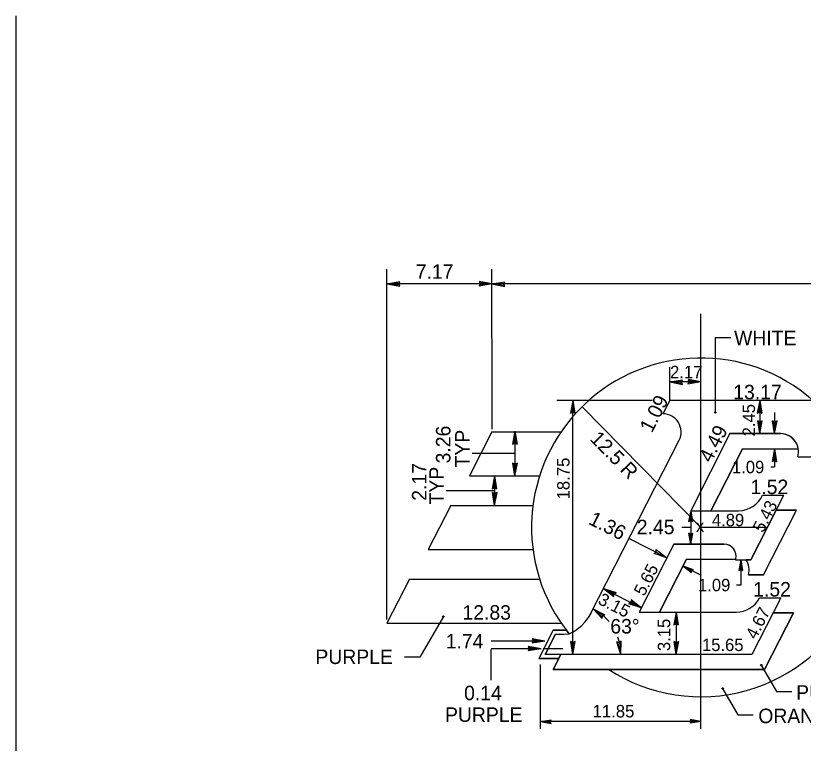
# Model space of a CAD drawing. Extents: x 10268197 to 10268826, y 2141503 to 2142677.
# Drawn here: x 10268664.32 to 10268696.97, y 2142401.45 to 2142431.59 of the extents above; entities that cross this region are included whole.
import ezdxf

# ---------------------------------------------------------------- set-up
doc = ezdxf.new("R2010")
doc.units = 0
doc.layers.add('Default', color=7, linetype='Continuous')
doc.layers.add('NonPlottingEle_dp', color=7, linetype='Continuous')

msp = doc.modelspace()

# ---------------------------------------------------------------- linework, layer by layer
at = {"layer": 'Default'}
for p, q in [((10268679.71, 2142406.582), (10268679.71, 2142421.09)), ((10268684.065, 2142415.347), (10268684.064, 2142421.09)), ((10268679.71, 2142420.48), (10268680.243, 2142420.574)), ((10268679.71, 2142420.48), (10268680.221, 2142420.524)), ((10268684.064, 2142420.48), (10268679.71, 2142420.48)), ((10268679.71, 2142420.48), (10268680.243, 2142420.386)), ((10268679.71, 2142420.48), (10268680.222, 2142420.435)), ((10268680.202, 2142420.48), (10268680.243, 2142420.574)), ((10268680.243, 2142420.386), (10268680.202, 2142420.48)), ((10268684.064, 2142420.48), (10268683.531, 2142420.574)), ((10268683.531, 2142420.574), (10268683.572, 2142420.48)), ((10268684.064, 2142420.48), (10268683.531, 2142420.386)), ((10268683.572, 2142420.48), (10268683.531, 2142420.386)), ((10268684.064, 2142420.48), (10268683.553, 2142420.524)), ((10268684.064, 2142420.48), (10268683.553, 2142420.435)), ((10268684.064, 2142420.48), (10268684.599, 2142420.565)), ((10268684.064, 2142420.48), (10268684.576, 2142420.516)), ((10268724.378, 2142420.48), (10268684.064, 2142420.48)), ((10268684.064, 2142420.48), (10268684.595, 2142420.377)), ((10268684.064, 2142420.48), (10268684.575, 2142420.426)), ((10268684.556, 2142420.471), (10268684.599, 2142420.565)), ((10268684.595, 2142420.377), (10268684.556, 2142420.471)), ((10268692.721, 2142410.391), (10268692.721, 2142419.238)), ((10268693.322, 2142418.257), (10268693.965, 2142418.258)), ((10268693.322, 2142415.153), (10268693.322, 2142418.257)), ((10268691.433, 2142415.653), (10268691.433, 2142417.027)), ((10268692.721, 2142416.417), (10268692.189, 2142416.52)), ((10268692.189, 2142416.52), (10268692.228, 2142416.425)), ((10268691.433, 2142416.417), (10268691.967, 2142416.501)), ((10268691.433, 2142416.417), (10268691.945, 2142416.453)), ((10268692.721, 2142416.417), (10268691.433, 2142416.417)), ((10268691.433, 2142416.417), (10268691.964, 2142416.314)), ((10268691.433, 2142416.417), (10268691.943, 2142416.363)), ((10268691.925, 2142416.408), (10268691.967, 2142416.501)), ((10268691.964, 2142416.314), (10268691.925, 2142416.408)), ((10268692.228, 2142416.425), (10268692.186, 2142416.332)), ((10268692.721, 2142416.417), (10268692.186, 2142416.332)), ((10268692.721, 2142416.417), (10268692.209, 2142416.381)), ((10268692.721, 2142416.417), (10268692.21, 2142416.47)), ((10268690.715, 2142415.653), (10268686.746, 2142415.654)), ((10268687.415, 2142415.653), (10268687.312, 2142415.122)), ((10268687.415, 2142415.653), (10268687.361, 2142415.142)), ((10268687.415, 2142405.129), (10268687.415, 2142415.653)), ((10268687.415, 2142415.653), (10268687.5, 2142415.119)), ((10268687.415, 2142415.653), (10268687.451, 2142415.141)), ((10268691.433, 2142415.653), (10268691.148, 2142415.096)), ((10268698.825, 2142415.653), (10268691.433, 2142415.653)), ((10268695.162, 2142415.653), (10268695.059, 2142415.122)), ((10268695.162, 2142415.653), (10268695.108, 2142415.142)), ((10268695.162, 2142415.653), (10268695.162, 2142414.275)), ((10268695.162, 2142415.653), (10268695.247, 2142415.119)), ((10268695.162, 2142415.653), (10268695.198, 2142415.141)), ((10268684.065, 2142414.457), (10268684.065, 2142415.347)), ((10268692.721, 2142410.391), (10268687.797, 2142415.39)), ((10268687.312, 2142415.122), (10268687.406, 2142415.161)), ((10268687.406, 2142415.161), (10268687.5, 2142415.119)), ((10268695.059, 2142415.122), (10268695.153, 2142415.161)), ((10268695.153, 2142415.161), (10268695.247, 2142415.119)), ((10268695.778, 2142415.155), (10268695.778, 2142414.275)), ((10268695.162, 2142414.275), (10268695.077, 2142414.81)), ((10268695.17, 2142414.768), (10268695.077, 2142414.81)), ((10268695.162, 2142414.275), (10268695.126, 2142414.787)), ((10268695.162, 2142414.275), (10268695.265, 2142414.807)), ((10268695.162, 2142414.275), (10268695.215, 2142414.786)), ((10268695.265, 2142414.807), (10268695.17, 2142414.768)), ((10268695.778, 2142414.275), (10268695.693, 2142414.81)), ((10268695.787, 2142414.767), (10268695.693, 2142414.81)), ((10268695.778, 2142414.275), (10268695.742, 2142414.787)), ((10268695.778, 2142414.275), (10268695.881, 2142414.807)), ((10268695.778, 2142414.275), (10268695.832, 2142414.786)), ((10268695.881, 2142414.807), (10268695.787, 2142414.767)), ((10268684.064, 2142414.351), (10268683.132, 2142412.521)), ((10268684.064, 2142414.351), (10268686.928, 2142414.351)), ((10268685.016, 2142414.374), (10268684.913, 2142413.843)), ((10268685.016, 2142414.374), (10268684.962, 2142413.864)), ((10268685.016, 2142414.374), (10268685.016, 2142412.521)), ((10268685.016, 2142414.374), (10268685.101, 2142413.84)), ((10268685.016, 2142414.374), (10268685.052, 2142413.862)), ((10268693.927, 2142414.275), (10268692.3, 2142411.08)), ((10268693.927, 2142414.275), (10268692.3, 2142411.08)), ((10268693.927, 2142414.275), (10268696.018, 2142414.275)), ((10268696.018, 2142414.275), (10268693.927, 2142414.275)), ((10268688.152, 2142406.806), (10268691.819, 2142414.003)), ((10268684.913, 2142413.843), (10268685.007, 2142413.882)), ((10268685.007, 2142413.882), (10268685.101, 2142413.84)), ((10268694.451, 2142413.649), (10268693.142, 2142411.08)), ((10268693.142, 2142411.08), (10268694.451, 2142413.649)), ((10268694.451, 2142413.649), (10268696.76, 2142413.649)), ((10268694.451, 2142413.649), (10268696.76, 2142413.649)), ((10268695.778, 2142413.649), (10268695.675, 2142413.118)), ((10268695.778, 2142413.649), (10268695.725, 2142413.138)), ((10268695.778, 2142413.649), (10268695.778, 2142412.898)), ((10268695.778, 2142413.649), (10268695.863, 2142413.114)), ((10268695.778, 2142413.649), (10268695.814, 2142413.137)), ((10268685.016, 2142413.448), (10268683.241, 2142413.448)), ((10268696.739, 2142413.309), (10268697.631, 2142413.31)), ((10268685.016, 2142412.521), (10268684.932, 2142413.055)), ((10268685.025, 2142413.013), (10268684.932, 2142413.055)), ((10268685.016, 2142412.521), (10268684.98, 2142413.033)), ((10268685.016, 2142412.521), (10268685.119, 2142413.052)), ((10268685.016, 2142412.521), (10268685.07, 2142413.031)), ((10268685.119, 2142413.052), (10268685.025, 2142413.013)), ((10268695.675, 2142413.118), (10268695.77, 2142413.157)), ((10268695.77, 2142413.157), (10268695.863, 2142413.114)), ((10268695.628, 2142412.898), (10268695.778, 2142412.898)), ((10268683.132, 2142412.521), (10268686.035, 2142412.521)), ((10268684.169, 2142412.521), (10268684.066, 2142411.989)), ((10268684.169, 2142412.521), (10268684.115, 2142412.01)), ((10268684.169, 2142412.521), (10268684.169, 2142411.3)), ((10268684.169, 2142412.521), (10268684.254, 2142411.986)), ((10268684.169, 2142412.521), (10268684.205, 2142412.009)), ((10268684.066, 2142411.989), (10268684.16, 2142412.029)), ((10268684.16, 2142412.029), (10268684.254, 2142411.986)), ((10268684.169, 2142411.911), (10268682.166, 2142411.911)), ((10268684.169, 2142411.3), (10268684.084, 2142411.835)), ((10268684.177, 2142411.792), (10268684.084, 2142411.835)), ((10268684.169, 2142411.3), (10268684.133, 2142411.812)), ((10268684.169, 2142411.3), (10268684.272, 2142411.832)), ((10268684.169, 2142411.3), (10268684.222, 2142411.811)), ((10268684.272, 2142411.832), (10268684.177, 2142411.792)), ((10268694.793, 2142409.051), (10268696.158, 2142411.731)), ((10268695.28, 2142411.731), (10268696.158, 2142411.731)), ((10268682.354, 2142411.3), (10268681.42, 2142409.47)), ((10268682.354, 2142411.3), (10268685.763, 2142411.3)), ((10268692.3, 2142411.08), (10268692.214, 2142410.637)), ((10268692.3, 2142411.08), (10268692.255, 2142410.654)), ((10268692.3, 2142411.08), (10268694.281, 2142411.08)), ((10268692.3, 2142411.08), (10268693.142, 2142411.08)), ((10268692.3, 2142411.08), (10268692.3, 2142409.702)), ((10268692.3, 2142411.08), (10268692.371, 2142410.634)), ((10268692.3, 2142411.08), (10268692.33, 2142410.653)), ((10268695.839, 2142411.104), (10268694.793, 2142409.051)), ((10268695.318, 2142408.425), (10268696.683, 2142411.105)), ((10268695.318, 2142408.425), (10268696.683, 2142411.105)), ((10268695.839, 2142411.104), (10268696.683, 2142411.105)), ((10268696.683, 2142411.105), (10268695.839, 2142411.104)), ((10268692.214, 2142410.637), (10268692.293, 2142410.669)), ((10268692.293, 2142410.669), (10268692.371, 2142410.634)), ((10268692.3, 2142410.391), (10268691.936, 2142410.391)), ((10268692.721, 2142402.042), (10268692.721, 2142410.391)), ((10268695.476, 2142410.391), (10268692.721, 2142410.391)), ((10268692.3, 2142409.702), (10268692.229, 2142410.148)), ((10268692.307, 2142410.113), (10268692.229, 2142410.148)), ((10268692.3, 2142409.702), (10268692.27, 2142410.129)), ((10268692.3, 2142409.702), (10268692.386, 2142410.145)), ((10268692.3, 2142409.702), (10268692.344, 2142410.128)), ((10268692.386, 2142410.145), (10268692.307, 2142410.113)), ((10268691.308, 2142409.134), (10268689.766, 2142409.92)), ((10268691.597, 2142409.702), (10268690.161, 2142406.883)), ((10268691.597, 2142409.702), (10268690.161, 2142406.883)), ((10268691.597, 2142409.702), (10268693.681, 2142409.702)), ((10268693.681, 2142409.702), (10268691.597, 2142409.702)), ((10268681.42, 2142409.47), (10268685.764, 2142409.47)), ((10268692.121, 2142409.076), (10268691.004, 2142406.883)), ((10268691.004, 2142406.883), (10268692.121, 2142409.076)), ((10268692.121, 2142409.076), (10268694.166, 2142409.076)), ((10268692.121, 2142409.076), (10268694.166, 2142409.076)), ((10268694.159, 2142409.051), (10268694.793, 2142409.051)), ((10268694.377, 2142409.051), (10268694.291, 2142408.608)), ((10268694.377, 2142409.051), (10268694.332, 2142408.625)), ((10268694.377, 2142409.051), (10268694.377, 2142408.003)), ((10268694.377, 2142409.051), (10268694.448, 2142408.605)), ((10268694.377, 2142409.051), (10268694.407, 2142408.624)), ((10268694.793, 2142409.051), (10268694.599, 2142409.052)), ((10268691.978, 2142408.793), (10268692.728, 2142408.411)), ((10268691.978, 2142408.793), (10268692.407, 2142408.654)), ((10268691.978, 2142408.793), (10268692.334, 2142408.516)), ((10268691.978, 2142408.793), (10268692.337, 2142408.56)), ((10268691.978, 2142408.793), (10268692.372, 2142408.626)), ((10268692.334, 2142408.516), (10268692.341, 2142408.601)), ((10268692.341, 2142408.601), (10268692.407, 2142408.654)), ((10268694.291, 2142408.608), (10268694.37, 2142408.641)), ((10268694.37, 2142408.641), (10268694.448, 2142408.605)), ((10268695.318, 2142408.425), (10268694.691, 2142408.425)), ((10268694.691, 2142408.425), (10268695.318, 2142408.425)), ((10268680.644, 2142408.25), (10268679.71, 2142406.419)), ((10268680.644, 2142408.25), (10268686.039, 2142408.25)), ((10268688.69, 2142407.861), (10268690.254, 2142407.064)), ((10268688.69, 2142407.861), (10268689.205, 2142407.694)), ((10268688.69, 2142407.861), (10268689.116, 2142407.528)), ((10268688.69, 2142407.861), (10268689.121, 2142407.582)), ((10268688.69, 2142407.861), (10268689.162, 2142407.66)), ((10268694.377, 2142408.003), (10268694.202, 2142408.003)), ((10268689.116, 2142407.528), (10268689.125, 2142407.63)), ((10268689.125, 2142407.63), (10268689.205, 2142407.694)), ((10268689.827, 2142407.397), (10268689.819, 2142407.295)), ((10268690.254, 2142407.064), (10268689.827, 2142407.397)), ((10268696.036, 2142407.473), (10268694.841, 2142405.129)), ((10268695.158, 2142407.473), (10268696.036, 2142407.473)), ((10268689.819, 2142407.295), (10268689.739, 2142407.231)), ((10268690.254, 2142407.064), (10268689.739, 2142407.231)), ((10268690.254, 2142407.064), (10268689.781, 2142407.265)), ((10268690.254, 2142407.064), (10268689.823, 2142407.344)), ((10268688.26, 2142407.011), (10268688.747, 2142406.775)), ((10268688.26, 2142407.011), (10268688.637, 2142406.623)), ((10268688.26, 2142407.011), (10268688.649, 2142406.675)), ((10268688.26, 2142407.011), (10268688.701, 2142406.748)), ((10268688.637, 2142406.623), (10268688.659, 2142406.723)), ((10268688.659, 2142406.723), (10268688.747, 2142406.775)), ((10268690.161, 2142406.883), (10268694.186, 2142406.883)), ((10268690.161, 2142406.883), (10268691.004, 2142406.883)), ((10268691.702, 2142406.883), (10268691.599, 2142406.351)), ((10268691.702, 2142406.883), (10268691.648, 2142406.372)), ((10268691.702, 2142406.883), (10268691.702, 2142405.129)), ((10268691.702, 2142406.883), (10268691.787, 2142406.348)), ((10268691.702, 2142406.883), (10268691.738, 2142406.371)), ((10268695.717, 2142406.846), (10268694.841, 2142405.129)), ((10268696.56, 2142406.846), (10268695.365, 2142404.502)), ((10268695.365, 2142404.502), (10268696.56, 2142406.846)), ((10268695.717, 2142406.846), (10268696.56, 2142406.846)), ((10268696.56, 2142406.846), (10268695.717, 2142406.846)), ((10268679.71, 2142406.419), (10268686.936, 2142406.419)), ((10268682.047, 2142406.698), (10268681.077, 2142405.018)), ((10268691.599, 2142406.351), (10268691.693, 2142406.39)), ((10268691.693, 2142406.39), (10268691.787, 2142406.348)), ((10268686.6, 2142406.138), (10268686.001, 2142404.961)), ((10268686.6, 2142406.138), (10268687.146, 2142406.138)), ((10268686.261, 2142405.678), (10268685.73, 2142405.781)), ((10268685.73, 2142405.781), (10268685.769, 2142405.686)), ((10268686.702, 2142405.971), (10268686.274, 2142405.129)), ((10268686.702, 2142405.971), (10268687.053, 2142405.971)), ((10268687.053, 2142405.971), (10268687.258, 2142405.987)), ((10268686.261, 2142405.678), (10268684.035, 2142405.678)), ((10268686.098, 2142405.359), (10268685.567, 2142405.462)), ((10268685.567, 2142405.462), (10268685.606, 2142405.367)), ((10268686.098, 2142405.359), (10268685.588, 2142405.412)), ((10268685.769, 2142405.686), (10268685.726, 2142405.593)), ((10268686.261, 2142405.678), (10268685.726, 2142405.593)), ((10268686.261, 2142405.678), (10268685.749, 2142405.642)), ((10268686.261, 2142405.678), (10268685.75, 2142405.731)), ((10268687.415, 2142405.129), (10268687.33, 2142405.663)), ((10268687.423, 2142405.621), (10268687.33, 2142405.663)), ((10268687.415, 2142405.129), (10268687.379, 2142405.64)), ((10268687.415, 2142405.129), (10268687.518, 2142405.66)), ((10268687.415, 2142405.129), (10268687.468, 2142405.639)), ((10268687.518, 2142405.66), (10268687.423, 2142405.621)), ((10268689.41, 2142405.132), (10268689.234, 2142405.644)), ((10268689.333, 2142405.618), (10268689.234, 2142405.644)), ((10268689.41, 2142405.132), (10268689.286, 2142405.63)), ((10268689.42, 2142405.673), (10268689.333, 2142405.618)), ((10268689.41, 2142405.132), (10268689.374, 2142405.644)), ((10268689.41, 2142405.132), (10268689.42, 2142405.673)), ((10268691.702, 2142405.129), (10268691.617, 2142405.663)), ((10268691.71, 2142405.621), (10268691.617, 2142405.663)), ((10268691.702, 2142405.129), (10268691.666, 2142405.64)), ((10268691.702, 2142405.129), (10268691.805, 2142405.66)), ((10268691.702, 2142405.129), (10268691.755, 2142405.639)), ((10268691.805, 2142405.66), (10268691.71, 2142405.621)), ((10268686.098, 2142405.359), (10268684.035, 2142405.359)), ((10268684.035, 2142404.056), (10268684.035, 2142405.339)), ((10268685.606, 2142405.367), (10268685.564, 2142405.274)), ((10268686.098, 2142405.359), (10268685.564, 2142405.274)), ((10268686.098, 2142405.359), (10268685.586, 2142405.323)), ((10268687, 2142405.359), (10268686.187, 2142405.359)), ((10268694.841, 2142405.129), (10268686.274, 2142405.129)), ((10268686.594, 2142404.502), (10268686.913, 2142405.129)), ((10268686.913, 2142405.129), (10268686.594, 2142404.502)), ((10268694.841, 2142405.129), (10268686.913, 2142405.129)), ((10268681.077, 2142405.018), (10268680.434, 2142405.017)), ((10268686.828, 2142404.961), (10268686.001, 2142404.961)), ((10268686.07, 2142402.042), (10268686.07, 2142404.715)), ((10268695.365, 2142404.502), (10268686.594, 2142404.502)), ((10268686.594, 2142404.502), (10268695.365, 2142404.502)), ((10268695.224, 2142404.685), (10268695.853, 2142403.595)), ((10268693.624, 2142403.717), (10268694.253, 2142402.627)), ((10268695.853, 2142403.595), (10268696.496, 2142403.595)), ((10268694.253, 2142402.627), (10268694.896, 2142402.627)), ((10268686.07, 2142402.348), (10268686.516, 2142402.419)), ((10268686.07, 2142402.348), (10268686.497, 2142402.378)), ((10268692.721, 2142402.348), (10268686.07, 2142402.348)), ((10268686.07, 2142402.348), (10268686.513, 2142402.262)), ((10268686.07, 2142402.348), (10268686.496, 2142402.303)), ((10268686.481, 2142402.341), (10268686.516, 2142402.419)), ((10268686.513, 2142402.262), (10268686.481, 2142402.341)), ((10268692.31, 2142402.355), (10268692.275, 2142402.278)), ((10268692.721, 2142402.348), (10268692.275, 2142402.278)), ((10268692.721, 2142402.348), (10268692.277, 2142402.434)), ((10268692.277, 2142402.434), (10268692.31, 2142402.355)), ((10268692.721, 2142402.348), (10268692.293, 2142402.319)), ((10268692.721, 2142402.348), (10268692.294, 2142402.393))]:
    msp.add_line(p, q, dxfattribs=at)
for points in [[(10268691.308, 2142409.134), (10268690.784, 2142409.305), (10268690.863, 2142409.37), (10268690.873, 2142409.473)], [(10268687.146, 2142406.138), (10268686.6, 2142406.138), (10268686.001, 2142404.961), (10268686.828, 2142404.961), (10268686.913, 2142405.129), (10268686.274, 2142405.129), (10268686.702, 2142405.971), (10268687.053, 2142405.971), (10268687.258, 2142405.987)]]:
    msp.add_lwpolyline(points, close=True, dxfattribs=at)
for centre in [(10268693.322, 2142415.153), (10268682.047, 2142406.699), (10268695.224, 2142404.685), (10268693.624, 2142403.717)]:
    msp.add_circle(centre, 0.0305, dxfattribs=at)
for centre, radius, start, end in [((10268692.721, 2142410.391), 7.017, 48.5904, 218.8792), ((10268691.15, 2142414.344), 0.752, 333.0033, 90.1042), ((10268696.019, 2142413.524), 0.752, 343.4611, 90), ((10268696.019, 2142413.524), 0.752, 9.5941, 90), ((10268694.282, 2142412.17), 1.09, 270, 336.2493), ((10268693.68, 2142409.201), 0.501, 342.6625, 90), ((10268693.68, 2142409.201), 0.501, 345.5225, 90), ((10268693.971, 2142408.639), 0.752, 343.4611, 33.2756), ((10268693.971, 2142408.639), 0.752, 343.4611, 33.2756), ((10268694.186, 2142407.979), 1.096, 270, 332.5096), ((10268692.721, 2142410.391), 7.017, 237.0648, 334.1734), ((10268686.538, 2142407.67), 1.831, 293.1567, 333.0112), ((10268687.298, 2142405.129), 2.113, 40.0298, 62.999), ((10268687.298, 2142405.129), 2.113, 0, 19.9667)]:
    msp.add_arc(centre, radius, start, end, dxfattribs=at)
at = {"layer": 'NonPlottingEle_dp'}
msp.add_line((10268664.322, 2142431.588), (10268664.322, 2142335.588), dxfattribs=at)

# ---------------------------------------------------------------- texts
at = {"layer": 'Default'}
for s, height, p in [('7.17', 0.5999, (10268680.906, 2142420.692)), ('WHITE', 0.5999, (10268694.1, 2142417.94)), ('2.17', 0.5142, (10268691.446, 2142416.57)), ('13.17', 0.5999, (10268694.066, 2142415.699)), ('1.09', 0.5142, (10268694.012, 2142412.635)), ('1.52', 0.5999, (10268694.782, 2142411.771)), ('4.89', 0.5142, (10268693.18, 2142410.439)), ('x', 0.517, (10268692.517, 2142410.196)), ('1.09', 0.5142, (10268692.605, 2142407.746)), ('1.52', 0.5999, (10268694.892, 2142407.528)), ('12.83', 0.5999, (10268682.842, 2142406.569)), ('63°', 0.5999, (10268688.969, 2142405.997)), ('1.74', 0.5999, (10268682.146, 2142405.376)), ('15.65', 0.5142, (10268692.769, 2142405.269)), ('PURPLE', 0.5999, (10268676.745, 2142404.73)), ('0.14', 0.5999, (10268682.908, 2142403.233)), ('PURPLE', 0.5999, (10268696.671, 2142403.254)), ('PURPLE', 0.5999, (10268682.117, 2142402.333)), ('11.85', 0.5174, (10268688.233, 2142402.518)), ('ORANGE', 0.5999, (10268695.103, 2142402.283))]:
    msp.add_text(s, height=height, dxfattribs=at).set_placement(p)
for s, height, rotation, p in [('1.09', 0.5999, 62.9854, (10268690.692, 2142414.276)), ('2.45', 0.5142, 90, (10268694.966, 2142414.163)), ('3.26', 0.5999, 90, (10268682.34, 2142413.044)), ('4.49', 0.5999, 63.012, (10268693.149, 2142413.032)), ('TYP', 0.5999, 90, (10268683.133, 2142412.875)), ('12.5 R', 0.5999, 314.5624, (10268688.09, 2142414.025)), ('18.75', 0.5174, 90, (10268687.281, 2142411.55)), ('2.17', 0.5999, 90, (10268681.347, 2142411.497)), ('TYP', 0.5999, 90, (10268682.065, 2142411.343)), ('5.43', 0.5142, 63.0087, (10268695.305, 2142410.142)), ('1.36', 0.5999, 333.0041, (10268688.025, 2142410.551)), ('2.45', 0.5999, 360, (10268690.067, 2142410.109)), ('5.65', 0.5142, 63.0001, (10268690.375, 2142407.513)), ('3.15', 0.5142, 333.0028, (10268688.42, 2142407.243)), ('4.67', 0.5142, 62.9952, (10268695.008, 2142405.718)), ('3.15', 0.5142, 90, (10268691.451, 2142405.268))]:
    msp.add_text(s, height=height, rotation=rotation, dxfattribs=at).set_placement(p)

doc.saveas('drawing.dxf')
